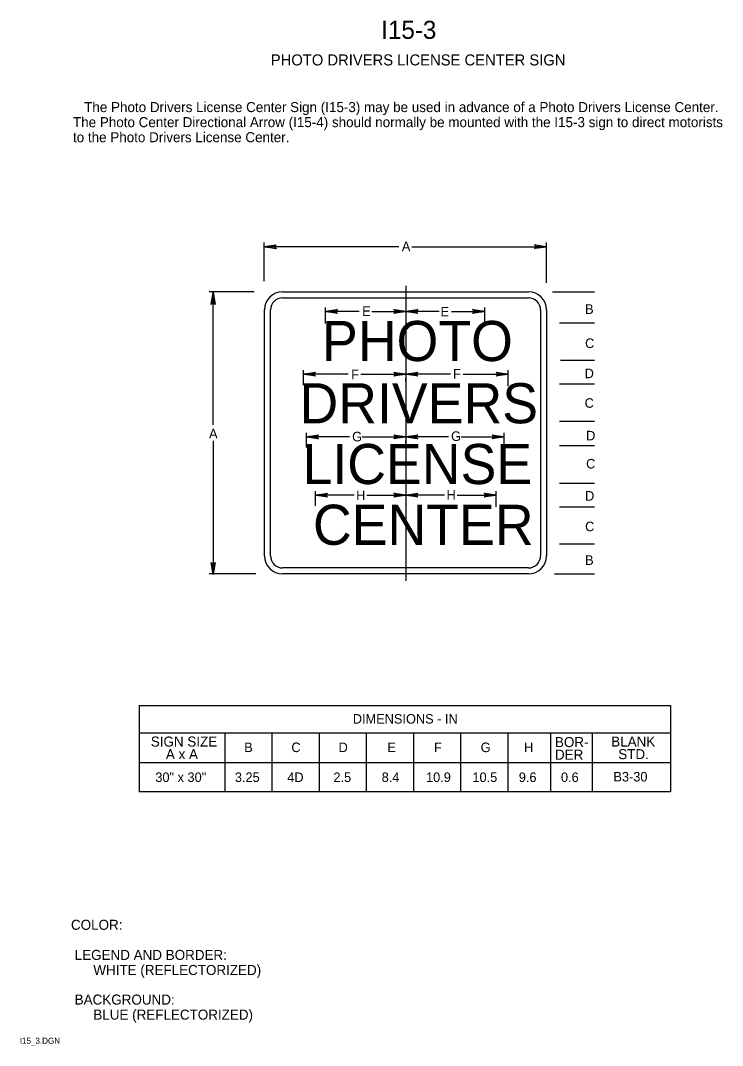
# Model space of a CAD drawing. Extents: x 0.013 to 0.187, y 0.004 to 0.259.
import ezdxf

# ---------------------------------------------------------------- set-up
doc = ezdxf.new("R2010")
doc.units = 0
for name, color, linetype in [('1', 7, 'Continuous'), ('2', 7, 'Continuous'), ('3', 7, 'Continuous')]:
    doc.layers.add(name, color=color, linetype=linetype)

# ---------------------------------------------------------------- blocks, each defined once
blk = doc.blocks.new('RARROW')
at = {"layer": '3'}
for p, q in [((-2.156, 0.285), (-2.2665, 0.384625)), ((-2.2665, 0.384625), (0, 0)), ((0, 0), (-2.2665, -0.379125)), ((-2.156, 0.285), (-2.075625, 0.12075)), ((0, 0), (-2.156, 0.285)), ((-2.14975, -0.2705), (0, 0)), ((-2.075625, 0.12075), (0, 0)), ((0, 0), (-2.074, -0.108)), ((-2.2665, -0.379125), (-2.14975, -0.2705)), ((-2.074, -0.108), (-2.14975, -0.2705))]:
    blk.add_line(p, q, dxfattribs=at)

msp = doc.modelspace()

# ---------------------------------------------------------------- linework, layer by layer
at = {"layer": '1'}
for p, q in [((0.10862, 0.19312), (0.10862, 0.11963)), ((0.14513, 0.19163), (0.15563, 0.19163)), ((0.14688, 0.18388), (0.15563, 0.18388)), ((0.14713, 0.17463), (0.15563, 0.17463)), ((0.14688, 0.16875), (0.15563, 0.16875)), ((0.14688, 0.15938), (0.15563, 0.15938)), ((0.14688, 0.15338), (0.15563, 0.15338)), ((0.14688, 0.144), (0.15563, 0.144)), ((0.14688, 0.13812), (0.15563, 0.13812)), ((0.14688, 0.12887), (0.15563, 0.12887)), ((0.14563, 0.12137), (0.15563, 0.12137))]:
    msp.add_line(p, q, dxfattribs=at)
at = {"layer": '3'}
for p, q in [((0.07337, 0.19425), (0.07337, 0.20388)), ((0.10687, 0.20287), (0.07337, 0.20287)), ((0.11013, 0.20287), (0.14363, 0.20287)), ((0.14363, 0.19387), (0.14363, 0.20388)), ((0.07088, 0.19163), (0.05963, 0.19163)), ((0.06062, 0.1585), (0.06062, 0.19163)), ((0.07792, 0.19162), (0.13917, 0.19162)), ((0.07792, 0.19012), (0.13917, 0.19012)), ((0.10862, 0.19013), (0.10862, 0.18575)), ((0.07342, 0.12587), (0.07342, 0.18712)), ((0.07492, 0.12587), (0.07492, 0.18712)), ((0.08862, 0.18375), (0.08862, 0.18775)), ((0.097, 0.18675), (0.08862, 0.18675)), ((0.10013, 0.18675), (0.10862, 0.18675)), ((0.11688, 0.18675), (0.10862, 0.18675)), ((0.12, 0.18675), (0.12825, 0.18675)), ((0.12825, 0.18338), (0.12825, 0.18775)), ((0.14217, 0.18712), (0.14217, 0.12587)), ((0.14367, 0.18712), (0.14367, 0.12587)), ((0.08313, 0.16837), (0.08313, 0.17213)), ((0.09425, 0.17112), (0.08313, 0.17112)), ((0.09738, 0.17112), (0.10862, 0.17112)), ((0.11975, 0.17112), (0.10862, 0.17112)), ((0.12287, 0.17112), (0.13412, 0.17112)), ((0.13412, 0.16812), (0.13412, 0.17213)), ((0.10862, 0.16937), (0.10862, 0.17012)), ((0.08388, 0.15288), (0.08388, 0.1565)), ((0.13312, 0.15288), (0.13312, 0.1565)), ((0.06062, 0.1545), (0.06062, 0.12137)), ((0.09463, 0.1555), (0.08388, 0.1555)), ((0.09775, 0.1555), (0.10862, 0.1555)), ((0.11925, 0.1555), (0.10862, 0.1555)), ((0.10862, 0.15388), (0.10862, 0.1545)), ((0.12237, 0.1555), (0.13312, 0.1555)), ((0.10862, 0.14388), (0.10862, 0.14)), ((0.08613, 0.13837), (0.08613, 0.142)), ((0.09575, 0.141), (0.08613, 0.141)), ((0.09888, 0.141), (0.10862, 0.141)), ((0.11825, 0.141), (0.10862, 0.141)), ((0.12137, 0.141), (0.13112, 0.141)), ((0.13112, 0.13812), (0.13112, 0.142)), ((0.13917, 0.12287), (0.07792, 0.12287)), ((0.07125, 0.12137), (0.05963, 0.12137)), ((0.13917, 0.12137), (0.07792, 0.12137)), ((0.04225, 0.08862), (0.1745, 0.08862)), ((0.04225, 0.08862), (0.04225, 0.06713)), ((0.1745, 0.08862), (0.1745, 0.06713)), ((0.1745, 0.08175), (0.04225, 0.08175)), ((0.06354, 0.08175), (0.06354, 0.06712)), ((0.07525, 0.08175), (0.07525, 0.06713)), ((0.087, 0.08175), (0.087, 0.06713)), ((0.09875, 0.08175), (0.09875, 0.06713)), ((0.1105, 0.08175), (0.1105, 0.06713)), ((0.12225, 0.08175), (0.12225, 0.06713)), ((0.134, 0.08175), (0.134, 0.06713)), ((0.14463, 0.08175), (0.14463, 0.06713)), ((0.15504, 0.08175), (0.15504, 0.06712)), ((0.1745, 0.07437), (0.04225, 0.07437)), ((0.1745, 0.06713), (0.04225, 0.06713))]:
    msp.add_line(p, q, dxfattribs=at)
for centre, radius, start, end in [((0.07792, 0.18712), 0.0045, 90, 180), ((0.13917, 0.18712), 0.0045, 0, 90), ((0.07792, 0.18712), 0.003, 90, 180), ((0.13917, 0.18712), 0.003, 0, 90), ((0.07792, 0.12587), 0.0045, 180, 270), ((0.07792, 0.12587), 0.003, 180, 270), ((0.13917, 0.12587), 0.0045, 270, 0), ((0.13917, 0.12587), 0.003, 270, 0)]:
    msp.add_arc(centre, radius, start, end, dxfattribs=at)

# ---------------------------------------------------------------- block references
at = {"layer": '3', "xscale": 0.0013236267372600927, "yscale": 0.001309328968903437}
for p, rotation in [((0.07337, 0.20287), 180), ((0.06062, 0.1915), 90), ((0.08862, 0.18675), 180), ((0.10862, 0.18675), 180), ((0.08313, 0.17112), 180), ((0.10862, 0.17112), 180), ((0.08388, 0.1555), 180), ((0.10862, 0.1555), 180), ((0.08613, 0.141), 180), ((0.10862, 0.141), 180), ((0.06062, 0.12125), -90)]:
    msp.add_blockref('RARROW', p, dxfattribs=dict(at, rotation=rotation))
for p in [(0.14363, 0.20287), (0.10862, 0.18675), (0.12825, 0.18675), (0.10862, 0.17112), (0.13412, 0.17112), (0.10862, 0.1555), (0.13312, 0.1555), (0.10862, 0.141), (0.13112, 0.141)]:
    msp.add_blockref('RARROW', p, dxfattribs=at)

# ---------------------------------------------------------------- texts
at = {"layer": '1'}
for s, height, p in [('I15-3', 0.0045, (0.1025, 0.25462)), ('PHOTO DRIVERS LICENSE CENTER SIGN', 0.0027503, (0.075, 0.248)), ('CENTER', 0.009991, (0.0855, 0.12862)), ('COLOR:', 0.0025, (0.02525, 0.03275)), (' LEGEND AND BORDER:', 0.0024998, (0.02525, 0.02525)), ('      WHITE (REFLECTORIZED)', 0.0024998, (0.02525, 0.0215)), (' BACKGROUND:', 0.0024998, (0.02525, 0.01413)), ('      BLUE (REFLECTORIZED)', 0.0024998, (0.02525, 0.01038)), ('I15_3.DGN', 0.0015, (0.0125, 0.00438))]:
    msp.add_text(s, height=height, dxfattribs=at).set_placement(p)
at = {"layer": '2'}
for s, height, p in [('   The Photo Drivers License Center Sign (I15-3) may be used in advance of a Photo Drivers License Center.', 0.00249975, (0.02575, 0.23638)), ('The Photo Center Directional Arrow (I15-4) should normally be mounted with the I15-3 sign to direct motorists', 0.00249975, (0.02575, 0.23263)), ('to the Photo Drivers License Center.', 0.0024998, (0.02575, 0.22888)), ('B', 0.00238, (0.15325, 0.18613)), ('PHOTO', 0.009993, (0.08775, 0.17438)), ('C', 0.00238, (0.15325, 0.17763)), ('D', 0.00238, (0.15313, 0.17012)), ('DRIVERS', 0.009993, (0.08213, 0.15888)), ('C', 0.00238, (0.15313, 0.16275)), ('D', 0.00238, (0.1535, 0.15463)), ('LICENSE', 0.009993, (0.08288, 0.14375)), ('C', 0.00238, (0.1535, 0.14763)), ('D', 0.00238, (0.15325, 0.13962)), ('C', 0.00238, (0.15325, 0.132)), ('B', 0.00238, (0.15325, 0.12362))]:
    msp.add_text(s, height=height, dxfattribs=at).set_placement(p)
at = {"layer": '3'}
for s, height, p in [('A', 0.00238, (0.10762, 0.20175)), ('E', 0.00238, (0.09775, 0.18563)), ('E', 0.00238, (0.11725, 0.1855)), ('F', 0.00238, (0.095, 0.16987)), ('F', 0.00238, (0.12037, 0.17)), ('A', 0.00238, (0.05963, 0.15513)), ('G', 0.00238, (0.09525, 0.15438)), ('G', 0.00238, (0.11988, 0.1545)), ('H', 0.00238, (0.09625, 0.13975)), ('H', 0.00238, (0.11875, 0.13987)), ('DIMENSIONS - IN', 0.0023752, (0.09542, 0.0841)), ('SIGN SIZE', 0.0025, (0.04512, 0.07838)), ('B', 0.00238, (0.06838, 0.077)), ('C', 0.00238, (0.08013, 0.077)), ('D', 0.00238, (0.09187, 0.077)), ('E', 0.00238, (0.10403, 0.077)), ('F', 0.00238, (0.11563, 0.077)), ('G', 0.00238, (0.12725, 0.077)), ('H', 0.00238, (0.13804, 0.077)), ('BOR-', 0.0025, (0.14575, 0.07825)), ('BLANK', 0.0025, (0.15975, 0.07838)), ('A x A', 0.0025, (0.04888, 0.07525)), ('DER', 0.0025, (0.14575, 0.07512)), ('STD.', 0.0025, (0.1615, 0.07525)), ('30" x 30"', 0.002375, (0.04625, 0.06956)), ('3.25', 0.002375, (0.06606, 0.06956)), ('4D', 0.002375, (0.0791, 0.06956)), ('2.5', 0.002375, (0.09059, 0.06956)), ('8.4', 0.002375, (0.10261, 0.06956)), ('10.9', 0.002375, (0.11365, 0.06956)), ('10.5', 0.002375, (0.1252, 0.06956)), ('9.6', 0.002375, (0.13674, 0.06956)), ('0.6', 0.002375, (0.14724, 0.06956)), ('B3-30', 0.002375, (0.1603, 0.06969))]:
    msp.add_text(s, height=height, dxfattribs=at).set_placement(p)

doc.saveas('drawing.dxf')
